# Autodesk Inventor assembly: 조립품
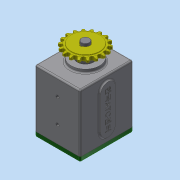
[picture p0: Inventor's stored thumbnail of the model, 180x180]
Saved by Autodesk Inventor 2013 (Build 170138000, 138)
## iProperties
Created: 2018-12
Part Number: 조립품
Document SubType Name: Assembly
Designer: dgall
Author: dgall
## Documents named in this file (16)
- C:\Users\dgall\Desktop\381207V1056\조립품.iam
- C:\Users\dgall\Desktop\381207V1056\본체.ipt
- C:\Users\dgall\Desktop\381207V1056\가변스프링.ipt
- C:\Users\dgall\Desktop\381207V1056\멈춤나사 M3x8.ipt
- C:\Users\dgall\Desktop\381207V1056\메인 기어 축.ipt
- C:\Users\dgall\Desktop\381207V1056\베어링 6003.ipt
- C:\Users\dgall\Desktop\381207V1056\부시.ipt
- C:\Users\dgall\Desktop\381207V1056\서브 기어 축.ipt
- C:\Users\dgall\Desktop\381207V1056\스프로킷.ipt
- C:\Users\dgall\Desktop\381207V1056\슬라이더.ipt
- C:\Users\dgall\Desktop\381207V1056\커버.ipt
- C:\Users\dgall\Desktop\381207V1056\키 5 x 5 x 18.ipt
- C:\Users\dgall\Desktop\381207V1056\베어링 608.ipt
- C:\Users\dgall\Desktop\381207V1056\오일 실 8 22 7.ipt
- C:\Users\dgall\Desktop\381207V1056\오일 실 17 32 8.ipt
- C:\Users\dgall\Desktop\381207V1056\볼트 M4 x 10.ipt
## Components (1 placed, 1 different names)
1. 가변스프링:1
